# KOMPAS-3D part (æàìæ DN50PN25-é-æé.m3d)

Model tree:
1. Объединить компоненты:1  (labels: СЕНС DN50PN25-В)
2. Эскиз:1
3. Операция выдавливания:1
     Расстояние 1 = 14
4. Фаска:1
     Угол = 45; Длина 1 = 2; Длина 2 = 2

Referenced files in D:\Савин\!СЕНСОР\3D для заказчика\!Новый перечень\СЕНС\3. СЕНС-В\DN50\: СЕНС DN50PN25-В.a3d
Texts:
  СЕНС DN50PN25-В-СВ
  ООО НПП Сенсор
  СЕНС DN50PN25-В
